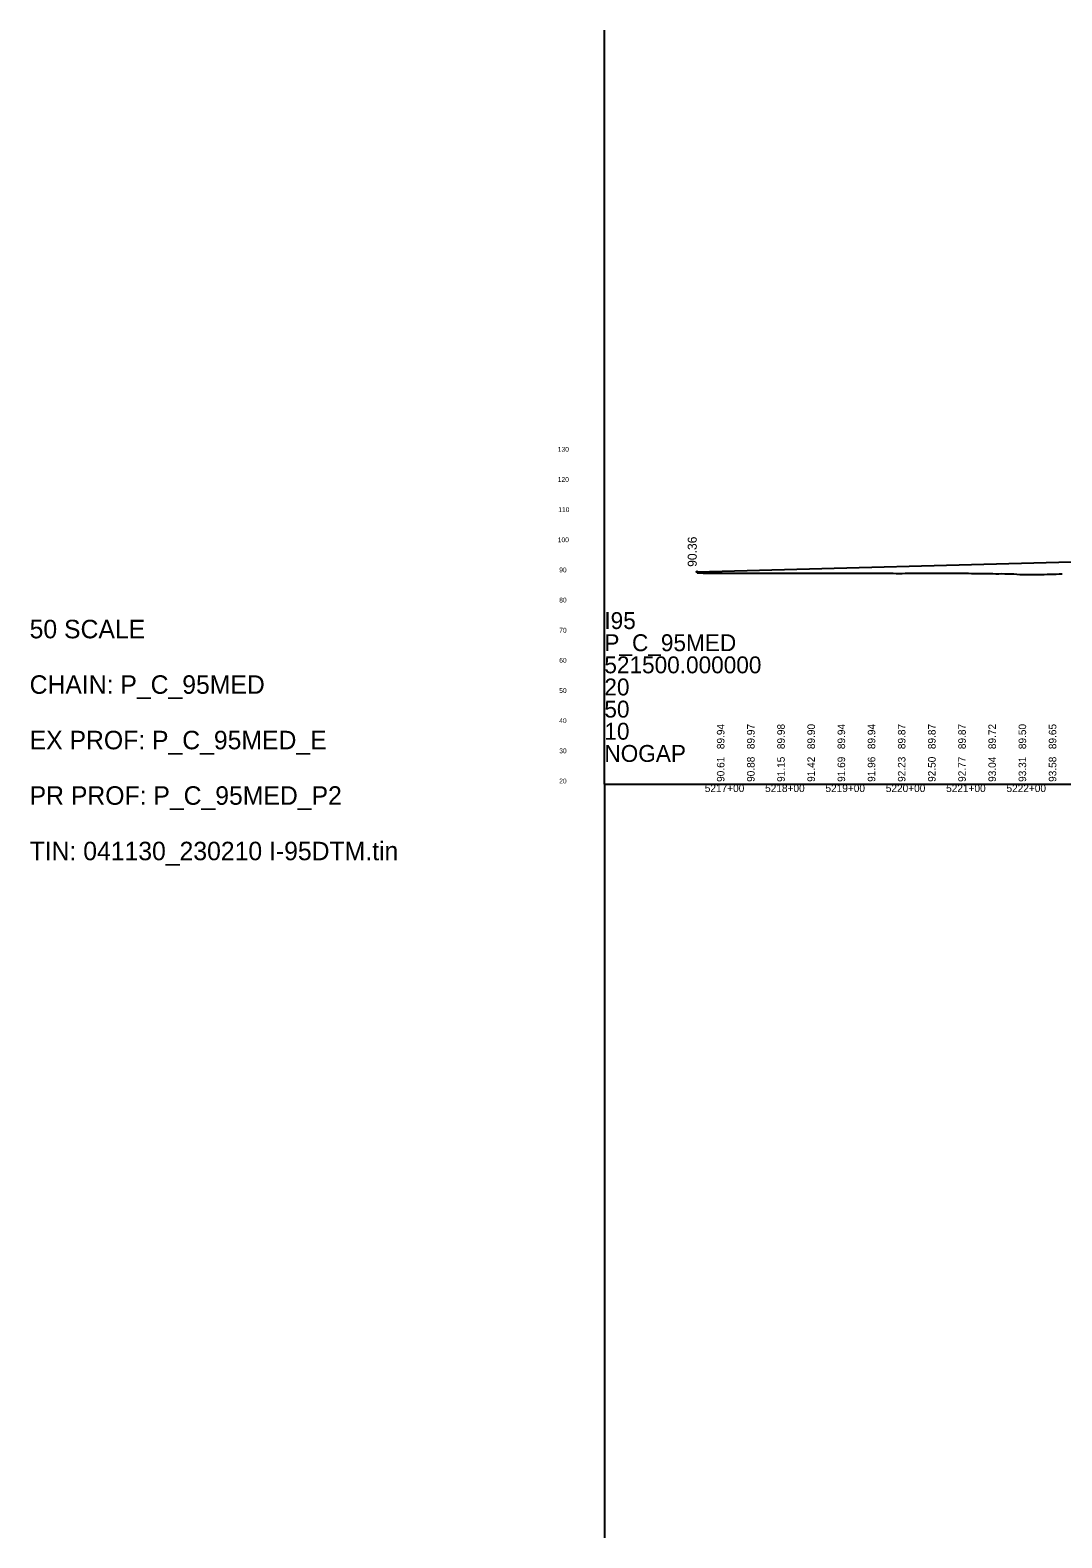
# Model space of a CAD drawing. Extents: x 2121671 to 2169879, y 557274 to 599957.
# Drawn here: x 2150116 to 2151826, y 577937 to 580437 of the extents above; entities that cross this region are included whole.
import ezdxf

# ---------------------------------------------------------------- set-up
doc = ezdxf.new("R2010")
doc.units = 0
for name, color, linetype in [('RD_DDB_ElevTX', 7, 'Continuous'), ('RD_DDB_GradeTX', 7, 'Continuous'), ('RD_DDB_Profile_EX', 7, 'Continuous'), ('RD_DDB_Profile_Lbl', 7, 'Continuous'), ('RD_DDB_Profile_PR', 7, 'Continuous'), ('RD_DDB_StaTX', 7, 'Continuous'), ('RD_DDB_StripGrade', 7, 'Continuous'), ('RD_GPK_Profile_Cell', 7, 'Continuous'), ('RD_HC_Data_Rel', 7, 'Continuous')]:
    doc.layers.add(name, color=color, linetype=linetype)

msp = doc.modelspace()

# ---------------------------------------------------------------- linework, layer by layer
at = {"layer": 'RD_DDB_GradeTX'}
msp.add_circle((2151221.5, 579538.6), 1, dxfattribs=at)
at = {"layer": 'RD_DDB_Profile_EX'}
for points in [[(2151221.5, 579536.9), (2151226.5, 579536.8), (2151231.5, 579536.7), (2151236.5, 579536.7), (2151241.5, 579536.6), (2151246.5, 579536.6), (2151251.5, 579536.6), (2151256.5, 579536.6), (2151261.5, 579536.6), (2151266.5, 579536.5), (2151271.5, 579536.5), (2151276.5, 579536.4), (2151281.5, 579536.5), (2151286.5, 579536.5), (2151291.5, 579536.5), (2151296.5, 579536.6), (2151301.5, 579536.6), (2151306.5, 579536.6), (2151311.5, 579536.6), (2151316.5, 579536.7), (2151321.5, 579536.7), (2151326.5, 579536.7), (2151331.5, 579536.7), (2151336.5, 579536.7), (2151341.5, 579536.6), (2151346.5, 579536.6), (2151351.5, 579536.7), (2151356.5, 579536.7), (2151361.5, 579536.7), (2151366.5, 579536.7), (2151371.5, 579536.7), (2151376.5, 579536.6), (2151381.5, 579536.6), (2151386.5, 579536.6), (2151391.5, 579536.6), (2151396.5, 579536.6), (2151401.5, 579536.5), (2151406.5, 579536.5), (2151411.5, 579536.4), (2151416.5, 579536.4), (2151421.5, 579536.4), (2151426.5, 579536.3), (2151431.5, 579536.3), (2151436.5, 579536.3), (2151441.5, 579536.4), (2151446.5, 579536.4), (2151451.5, 579536.5), (2151456.5, 579536.5), (2151461.5, 579536.5), (2151466.5, 579536.5), (2151471.5, 579536.5), (2151476.5, 579536.6), (2151481.5, 579536.6), (2151486.5, 579536.7), (2151491.5, 579536.7), (2151496.5, 579536.7), (2151501.5, 579536.7), (2151506.5, 579536.6), (2151511.5, 579536.6), (2151516.5, 579536.5), (2151521.5, 579536.5), (2151526.5, 579536.4), (2151531.5, 579536.4), (2151536.5, 579536.3), (2151541.5, 579536.3), (2151546.5, 579536.2), (2151551.5, 579536.1), (2151556.5, 579536.1), (2151561.5, 579536.1), (2151566.5, 579536.2), (2151571.5, 579536.2), (2151576.5, 579536.2), (2151581.5, 579536.2), (2151586.5, 579536.2), (2151591.5, 579536.2), (2151596.5, 579536.2), (2151601.5, 579536.2), (2151606.5, 579536.2), (2151611.5, 579536.2), (2151616.5, 579536.2), (2151621.5, 579536.2), (2151626.5, 579536.2), (2151631.5, 579536.2), (2151636.5, 579536.3), (2151641.5, 579536.3), (2151646.5, 579536.2), (2151651.5, 579536.2), (2151656.5, 579536.2), (2151661.5, 579536.2), (2151666.5, 579536.2), (2151671.5, 579536.2), (2151676.5, 579536.1), (2151681.5, 579536.1), (2151686.5, 579536.1), (2151691.5, 579536), (2151696.5, 579535.9), (2151701.5, 579535.9), (2151706.5, 579535.8), (2151711.5, 579535.7), (2151716.5, 579535.4), (2151721.5, 579535.4)], [(2151721.5, 579535.4), (2151726.5, 579535.6), (2151731.5, 579535.5), (2151736.5, 579535.4), (2151741.5, 579535.3), (2151746.5, 579535.2), (2151751.5, 579534.5), (2151756.5, 579534.4), (2151761.5, 579534.4), (2151766.5, 579534.4), (2151771.5, 579534.3), (2151776.5, 579534.3), (2151781.5, 579534.3), (2151786.5, 579534.2), (2151791.5, 579534.3), (2151796.5, 579534.3), (2151801.5, 579534.5), (2151806.5, 579534.6), (2151811.5, 579534.7), (2151816.5, 579535), (2151821.5, 579535.3), (2151826.5, 579535.3)]]:
    msp.add_lwpolyline(points, dxfattribs=at)
at = {"layer": 'RD_DDB_Profile_PR'}
msp.add_line((2151221.5, 579538.6), (2152067.8, 579561.5), dxfattribs=at)
at = {"layer": 'RD_GPK_Profile_Cell'}
for q in [(2151067.9, 580436.8), (2157367.9, 579186.8), (2151067.9, 577936.8)]:
    msp.add_line((2151067.9, 579186.8), q, dxfattribs=at)

# ---------------------------------------------------------------- texts
at = {"layer": 'RD_DDB_ElevTX'}
for s, p in [('130', (2150990.7, 579737.8)), ('120', (2150990.7, 579687.8)), ('110', (2150991.5, 579637.8)), ('100', (2150990.7, 579587.8)), ('90', (2150993.1, 579537.8)), ('80', (2150993.1, 579487.8)), ('70', (2150993.1, 579437.8)), ('60', (2150993.1, 579387.8)), ('50', (2150993.1, 579337.8)), ('40', (2150993.1, 579287.8)), ('30', (2150993.1, 579237.8)), ('20', (2150993.1, 579187.8))]:
    msp.add_text(s, height=8, dxfattribs=at).set_placement(p)
at = {"layer": 'RD_DDB_Profile_Lbl'}
msp.add_text('90.36', height=15, rotation=90, dxfattribs=at).set_placement((2151221, 579546.9))
at = {"layer": 'RD_DDB_StaTX'}
for s, p in [('5217+00', (2151234.3, 579173.5)), ('5218+00', (2151334.3, 579173.5)), ('5219+00', (2151434.3, 579173.5)), ('5220+00', (2151534.3, 579173.5)), ('5221+00', (2151634.3, 579173.5)), ('5222+00', (2151734.3, 579173.5))]:
    msp.add_text(s, height=12.5, dxfattribs=at).set_placement(p)
at = {"layer": 'RD_DDB_StripGrade'}
for s, p in [('89.94', (2151266.9, 579244.6)), ('89.97', (2151316.9, 579244.6)), ('89.98', (2151366.9, 579244.6)), ('89.90', (2151416.9, 579244.6)), ('89.94', (2151466.9, 579244.6)), ('89.94', (2151516.9, 579244.6)), ('89.87', (2151566.9, 579244.6)), ('89.87', (2151616.9, 579244.6)), ('89.87', (2151666.9, 579244.6)), ('89.72', (2151716.9, 579244.6)), ('89.50', (2151766.9, 579244.6)), ('89.65', (2151816.9, 579244.6)), ('90.61', (2151266.9, 579190.3)), ('90.88', (2151316.9, 579190.3)), ('91.15', (2151366.9, 579190.3)), ('91.42', (2151416.9, 579190.3)), ('91.69', (2151466.9, 579190.3)), ('91.96', (2151516.9, 579190.3)), ('92.23', (2151566.9, 579190.3)), ('92.50', (2151616.9, 579190.3)), ('92.77', (2151666.9, 579190.3)), ('93.04', (2151716.9, 579190.3)), ('93.31', (2151766.9, 579190.3)), ('93.58', (2151816.9, 579190.3))]:
    msp.add_text(s, height=12.5, rotation=90, dxfattribs=at).set_placement(p)
at = {"layer": 'RD_GPK_Profile_Cell'}
for s, p in [('I95', (2151067.9, 579443.8)), ('P_C_95MED', (2151067.9, 579407.1)), ('521500.000000', (2151067.9, 579370.4)), ('20', (2151067.9, 579333.7)), ('50', (2151067.9, 579297)), ('10', (2151067.9, 579260.3)), ('NOGAP', (2151067.9, 579223.5))]:
    msp.add_text(s, height=28, dxfattribs=at).set_placement(p)
at = {"layer": 'RD_HC_Data_Rel'}
for s, height, p in [('50 SCALE', 30.67, (2150115.4, 579428.4)), ('CHAIN: P_C_95MED', 30.668, (2150115.4, 579336.4)), ('EX PROF: P_C_95MED_E', 30.668, (2150115.4, 579244.4)), ('PR PROF: P_C_95MED_P2', 30.668, (2150115.4, 579152.4)), ('TIN: 041130_230210 I-95DTM.tin', 30.668, (2150115.4, 579060.4))]:
    msp.add_text(s, height=height, rotation=360, dxfattribs=at).set_placement(p)

doc.saveas('drawing.dxf')
